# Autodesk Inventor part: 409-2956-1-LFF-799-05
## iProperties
Created: 2010-11
Part Number: 409-2956-1-LFF-799-05
Material: 3/4" OD TUBE - SS
Document SubType Name: Modeling
Designer: S. Boerckel
Engineer: Steve Boerckel
Mass: 726.732 g
Surface Area: 1091.35 cm^2
Volume: 89.9421 cm^3
Density: 8.08 g/cm^3
Description: DRAIN TUBING
LGTH: 39.238 in
Author: S. Boerckel
Revision Number: 0
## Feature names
1. TaggingFeature1
